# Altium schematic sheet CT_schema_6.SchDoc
size 256 x 245 mm
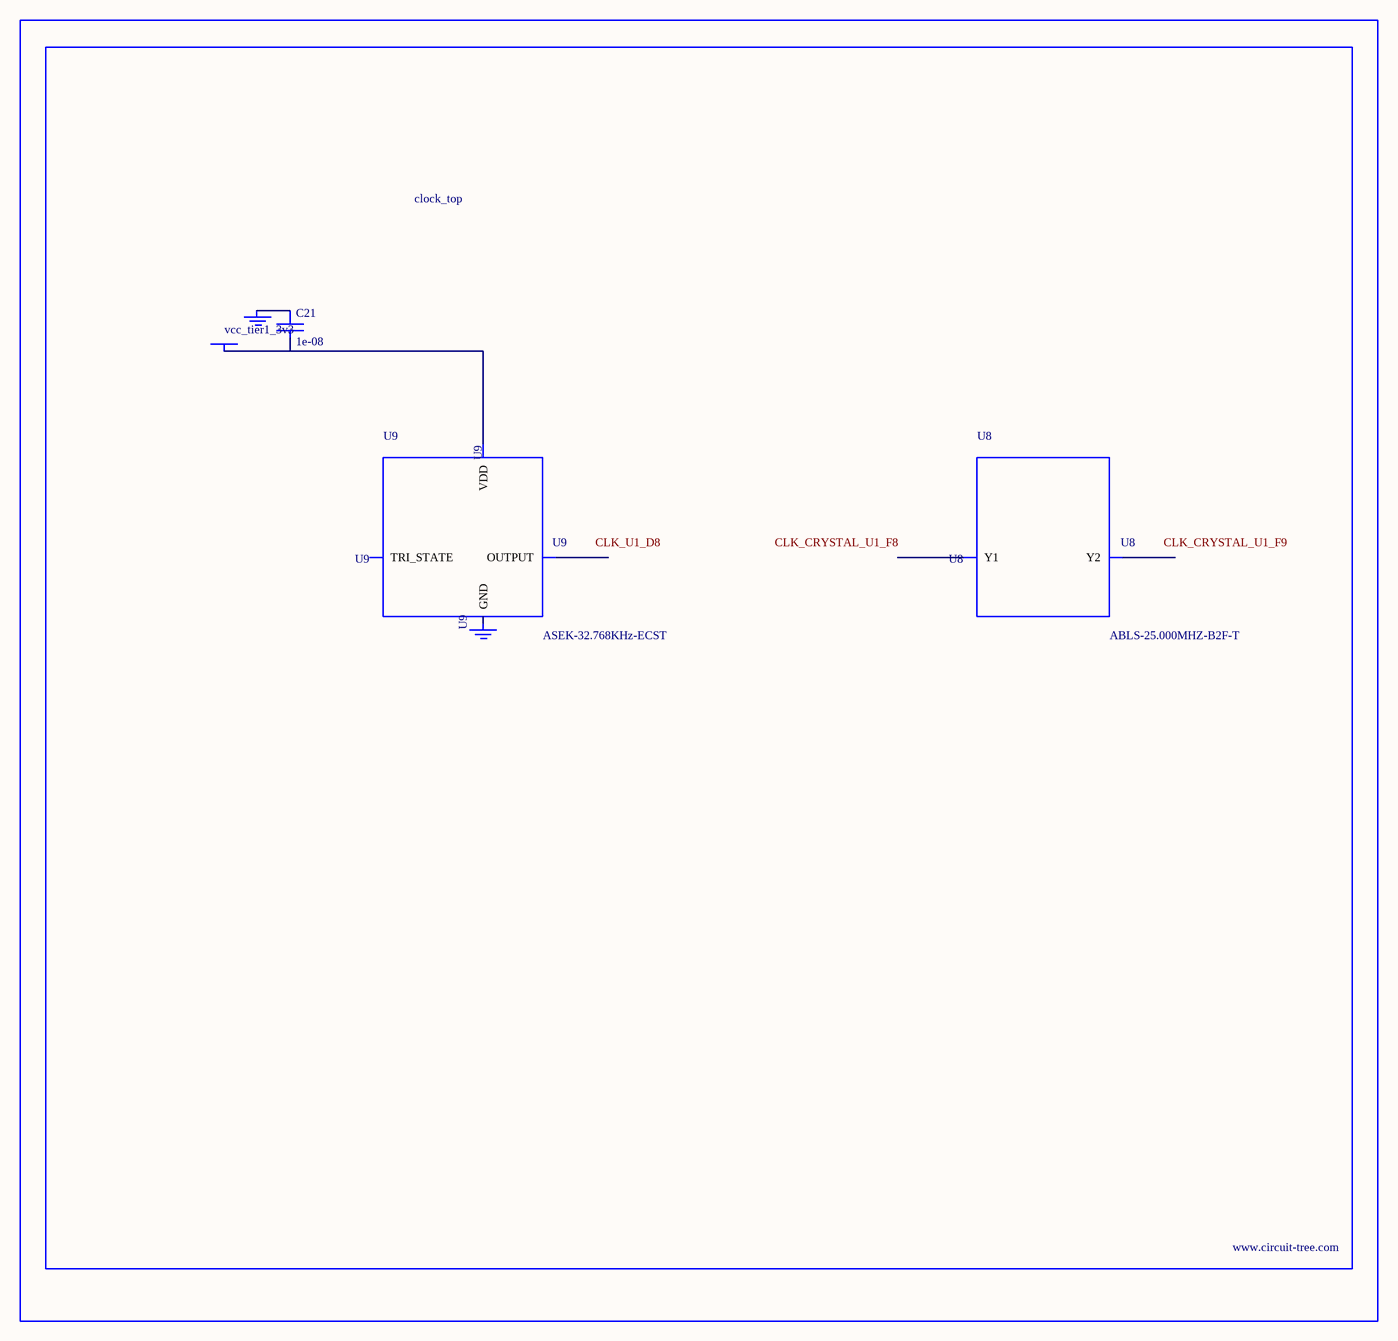
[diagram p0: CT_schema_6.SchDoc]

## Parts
BORDER5  (no value)
C21  1e-08  [C0402]
GND_INSTANCE_5_0  (no value)
GND_INSTANCE_5_1  (no value)
POWER_INSTANCE_5_0  vcc_tier1_3v3
U8  ABLS-25.000MHZ-B2F-T  [ABLS-25.000MHZ-B2F-T]
U9  ASEK-32.768KHz-ECST  [ASEK]

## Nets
NetC21_1: C21.1 GND_INSTANCE_5_0.0(GND)
NetC21_2: C21.2 POWER_INSTANCE_5_0.0(PWR) U9.4(VDD)

Not connected (* = marked no-connect by the designer): GND_INSTANCE_5_1 0(GND); U8 1(Y1) 2(Y2); U9 1(TRI_STATE) 2(GND) 3(OUTPUT)

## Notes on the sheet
- Labels drawn without touching a wire or pin: CLK_CRYSTAL_U1_F8, CLK_CRYSTAL_U1_F9, CLK_U1_D8

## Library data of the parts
BORDER5 = BORDER_PAGE5
C21 = C0402C103K3RAC
GND_INSTANCE_5_0 GND_INSTANCE_5_1 = GND
POWER_INSTANCE_5_0 = PWR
